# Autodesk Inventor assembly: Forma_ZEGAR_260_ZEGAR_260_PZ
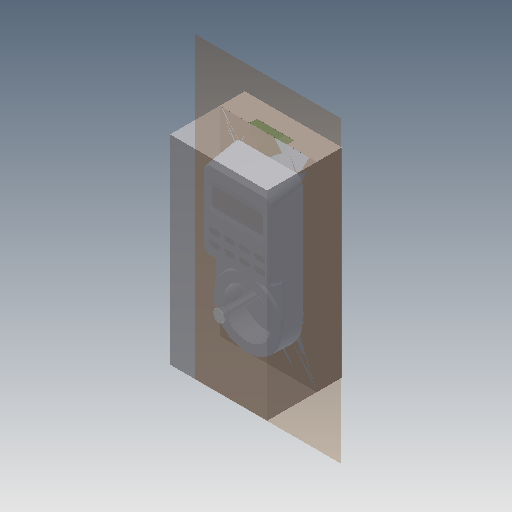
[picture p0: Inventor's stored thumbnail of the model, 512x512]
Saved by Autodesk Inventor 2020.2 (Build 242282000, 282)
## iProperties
Created: 2015-01
Part Number: Forma_ZEGAR_260_ZEGAR_260_PZ
Document SubType Name: Assembly
Designer: F.Stasiak
Catalog Web Link: www.expertbooks.pl
Manager: www.cadconsulting.pl
Company: Fabian Stasiak CAD Consulting
Author: F.Stasiak
Subject: Zbiór ćwiczeń. Autodesk Inventor 2020. Kurs Professional
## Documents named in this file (11)
- C:\2020_Kurs_Professional\R6 Formy\Komponenty\Forma_ZEGAR_260_ZEGAR_260_PZ.iam
- C:\2020_Kurs_Professional\R6 Formy\Komponenty\Forma_ZEGAR_260_ZEGAR_260_MP.ipt
- C:\2020_Kurs_Professional\R6 Formy\Komponenty\Forma_ZEGAR_260_ZEGAR_260_WP.ipt
- C:\2020_Kurs_Professional\R6 Formy\Komponenty\Forma_ZEGAR_260_ZEGAR_260_CR_Base.ipt
- C:\2020_Kurs_Professional\R6 Formy\Komponenty\Forma_ZEGAR_260_ZEGAR_260_CV_Base.ipt
- C:\2020_Kurs_Professional\R6 Formy\Komponenty\Forma_ZEGAR_260_ZEGAR_260_CV_1.ipt
- C:\2020_Kurs_Professional\R6 Formy\Komponenty\Forma_ZEGAR_260_ZEGAR_260_CR_1.ipt
- C:\2020_Kurs_Professional\R6 Formy\Komponenty\Rdzenie formujące\PUNCH_CDH\Forma_ZEGAR_260_ZEGAR_260_Rdzeń formujący8_Base.ipt
- C:\2020_Kurs_Professional\R6 Formy\Komponenty\Rdzenie formujące\PUNCH_CDH\Forma_ZEGAR_260_ZEGAR_260_Rdzeń formujący8_1.ipt
- C:\2020_Kurs_Professional\R6 Formy\Komponenty\Forma_ZEGAR_260_ZEGAR_260_IN2_Base.ipt
- C:\2020_Kurs_Professional\R6 Formy\Komponenty\Forma_ZEGAR_260_ZEGAR_260_IN2_1_1.ipt
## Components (10 placed, 10 different names)
1. Forma_ZEGAR_260_ZEGAR_260_MP:1 — Równoległy:1, Równoległy:2, Równoległy:3, Równoległy:4, Równoległy:5, Równoległy:6
2. Forma_ZEGAR_260_ZEGAR_260_WP:1 — Równoległy:4, Równoległy:5, Równoległy:6
3. Forma_ZEGAR_260_ZEGAR_260_CR_Base:1 — Równoległy:7, Równoległy:8, Równoległy:9, Równoległy:13, Równoległy:14, Równoległy:15
4. Forma_ZEGAR_260_ZEGAR_260_CR_1:1 — Równoległy:13, Równoległy:14, Równoległy:15, Równoległy:32, Równoległy:33, Równoległy:34
5. Forma_ZEGAR_260_ZEGAR_260_CV_Base:1 — Równoległy:10, Równoległy:11, Równoległy:12, Równoległy:16, Równoległy:17, Równoległy:18
6. Forma_ZEGAR_260_ZEGAR_260_CV_1:1 — Równoległy:16, Równoległy:17, Równoległy:18, Równoległy:23, Równoległy:24, Równoległy:25
7. Forma_ZEGAR_260_ZEGAR_260_Rdzeń formujący8_Base:1 — Kąt:1, Równoległy:20, Równoległy:21, Równoległy:22, Równoległy:35
8. Forma_ZEGAR_260_ZEGAR_260_Rdzeń formujący8_1:1 — Równoległy:20, Równoległy:21, Równoległy:22, Równoległy:23, Równoległy:24, Równoległy:25
9. Forma_ZEGAR_260_ZEGAR_260_IN2_Base:1 — Równoległy:26, Równoległy:27, Równoległy:28, Równoległy:29, Równoległy:30, Równoległy:31
10. Forma_ZEGAR_260_ZEGAR_260_IN2_1_1:1 — Równoległy:29, Równoległy:30, Równoległy:31, Równoległy:32, Równoległy:33, Równoległy:34
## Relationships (35: Flush 34, Angle 1)
- Równoległy:1 [Flush]: Forma_ZEGAR_260_ZEGAR_260_MP:1
- Równoległy:2 [Flush]: Forma_ZEGAR_260_ZEGAR_260_MP:1
- Równoległy:3 [Flush]: Forma_ZEGAR_260_ZEGAR_260_MP:1
- Równoległy:4 [Flush]: Forma_ZEGAR_260_ZEGAR_260_MP:1 ↔ Forma_ZEGAR_260_ZEGAR_260_WP:1
- Równoległy:5 [Flush]: Forma_ZEGAR_260_ZEGAR_260_MP:1 ↔ Forma_ZEGAR_260_ZEGAR_260_WP:1
- Równoległy:6 [Flush]: Forma_ZEGAR_260_ZEGAR_260_MP:1 ↔ Forma_ZEGAR_260_ZEGAR_260_WP:1
- Równoległy:7 [Flush]: Forma_ZEGAR_260_ZEGAR_260_CR_Base:1
- Równoległy:8 [Flush]: Forma_ZEGAR_260_ZEGAR_260_CR_Base:1
- Równoległy:9 [Flush]: Forma_ZEGAR_260_ZEGAR_260_CR_Base:1
- Równoległy:10 [Flush]: Forma_ZEGAR_260_ZEGAR_260_CV_Base:1
- Równoległy:11 [Flush]: Forma_ZEGAR_260_ZEGAR_260_CV_Base:1
- Równoległy:12 [Flush]: Forma_ZEGAR_260_ZEGAR_260_CV_Base:1
- Równoległy:13 [Flush]: Forma_ZEGAR_260_ZEGAR_260_CR_Base:1 ↔ Forma_ZEGAR_260_ZEGAR_260_CR_1:1
- Równoległy:14 [Flush]: Forma_ZEGAR_260_ZEGAR_260_CR_Base:1 ↔ Forma_ZEGAR_260_ZEGAR_260_CR_1:1
- Równoległy:15 [Flush]: Forma_ZEGAR_260_ZEGAR_260_CR_Base:1 ↔ Forma_ZEGAR_260_ZEGAR_260_CR_1:1
- Równoległy:16 [Flush]: Forma_ZEGAR_260_ZEGAR_260_CV_Base:1 ↔ Forma_ZEGAR_260_ZEGAR_260_CV_1:1
- Równoległy:17 [Flush]: Forma_ZEGAR_260_ZEGAR_260_CV_Base:1 ↔ Forma_ZEGAR_260_ZEGAR_260_CV_1:1
- Równoległy:18 [Flush]: Forma_ZEGAR_260_ZEGAR_260_CV_Base:1 ↔ Forma_ZEGAR_260_ZEGAR_260_CV_1:1
- Kąt:1 [Angle]: Forma_ZEGAR_260_ZEGAR_260_Rdzeń formujący8_Base:1
- Równoległy:20 [Flush]: Forma_ZEGAR_260_ZEGAR_260_Rdzeń formujący8_Base:1 ↔ Forma_ZEGAR_260_ZEGAR_260_Rdzeń formujący8_1:1
- Równoległy:21 [Flush]: Forma_ZEGAR_260_ZEGAR_260_Rdzeń formujący8_Base:1 ↔ Forma_ZEGAR_260_ZEGAR_260_Rdzeń formujący8_1:1
- Równoległy:22 [Flush]: Forma_ZEGAR_260_ZEGAR_260_Rdzeń formujący8_Base:1 ↔ Forma_ZEGAR_260_ZEGAR_260_Rdzeń formujący8_1:1
- Równoległy:23 [Flush]: Forma_ZEGAR_260_ZEGAR_260_CV_1:1 ↔ Forma_ZEGAR_260_ZEGAR_260_Rdzeń formujący8_1:1
- Równoległy:24 [Flush]: Forma_ZEGAR_260_ZEGAR_260_CV_1:1 ↔ Forma_ZEGAR_260_ZEGAR_260_Rdzeń formujący8_1:1
- Równoległy:25 [Flush]: Forma_ZEGAR_260_ZEGAR_260_CV_1:1 ↔ Forma_ZEGAR_260_ZEGAR_260_Rdzeń formujący8_1:1
- Równoległy:26 [Flush]: Forma_ZEGAR_260_ZEGAR_260_IN2_Base:1
- Równoległy:27 [Flush]: Forma_ZEGAR_260_ZEGAR_260_IN2_Base:1
- Równoległy:28 [Flush]: Forma_ZEGAR_260_ZEGAR_260_IN2_Base:1
- Równoległy:29 [Flush]: Forma_ZEGAR_260_ZEGAR_260_IN2_Base:1 ↔ Forma_ZEGAR_260_ZEGAR_260_IN2_1_1:1
- Równoległy:30 [Flush]: Forma_ZEGAR_260_ZEGAR_260_IN2_Base:1 ↔ Forma_ZEGAR_260_ZEGAR_260_IN2_1_1:1
- Równoległy:31 [Flush]: Forma_ZEGAR_260_ZEGAR_260_IN2_Base:1 ↔ Forma_ZEGAR_260_ZEGAR_260_IN2_1_1:1
- Równoległy:32 [Flush]: Forma_ZEGAR_260_ZEGAR_260_CR_1:1 ↔ Forma_ZEGAR_260_ZEGAR_260_IN2_1_1:1
- Równoległy:33 [Flush]: Forma_ZEGAR_260_ZEGAR_260_CR_1:1 ↔ Forma_ZEGAR_260_ZEGAR_260_IN2_1_1:1
- Równoległy:34 [Flush]: Forma_ZEGAR_260_ZEGAR_260_CR_1:1 ↔ Forma_ZEGAR_260_ZEGAR_260_IN2_1_1:1
- Równoległy:35 [Flush]: Forma_ZEGAR_260_ZEGAR_260_Rdzeń formujący8_Base:1
